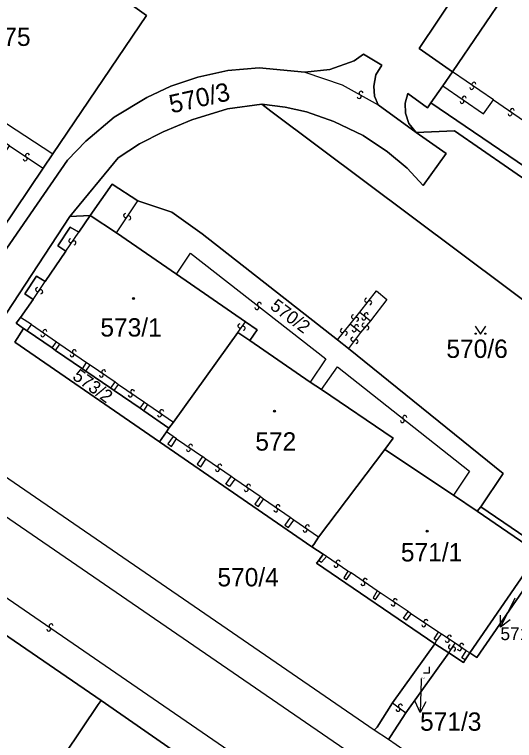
# Model space of a CAD drawing. Extents: x -600309 to -598967, y -1161267 to -1160292.
# Drawn here: x -600269.6 to -600223.2, y -1160535.7 to -1160468.5 of the extents above; entities that cross this region are included whole.
import ezdxf

# ---------------------------------------------------------------- set-up
doc = ezdxf.new("R2010")
doc.units = 0
for name, color, linetype in [('Level 1', 7, 'Continuous'), ('Level 13', 7, 'Continuous'), ('Level 3', 7, 'Continuous'), ('Level 4', 7, 'Continuous'), ('Level 5', 7, 'Continuous'), ('Level 57', 7, 'Continuous'), ('Level 60', 7, 'Continuous'), ('Vrstva 60', 7, 'Continuous')]:
    doc.layers.add(name, color=color, linetype=linetype)

msp = doc.modelspace()

# ---------------------------------------------------------------- linework, layer by layer
at = {"layer": 'Level 1'}
for points in [[(-600229, -1160473.78), (-600232.09, -1160471.61), (-600221.5, -1160455.83), (-600220, -1160454.31), (-600213.07, -1160456.09), (-600210.39, -1160453.38)], [(-600266.04, -1160481.38), (-600257.33, -1160468.55), (-600273.4, -1160457.1)], [(-600210.13, -1160470.07), (-600221.28, -1160462.46), (-600229, -1160473.78)], [(-600242.67, -1160473.81), (-600240.34, -1160473.56), (-600238.1, -1160472.77), (-600237.22, -1160472.15), (-600235.52, -1160473.17), (-600236.08, -1160474.07), (-600236.29, -1160475.1), (-600236.21, -1160476.03), (-600235.87, -1160476.84)], [(-600242.67, -1160473.81), (-600246.89, -1160473.4), (-600249.82, -1160473.65), (-600252.59, -1160474.29), (-600255.09, -1160475.12), (-600257.31, -1160476.17), (-600260.33, -1160477.98), (-600262.97, -1160480.2), (-600264.66, -1160481.97), (-600272.84, -1160493.8), (-600275.6, -1160500.4), (-600277.27, -1160506.1), (-600277.44, -1160506.49)], [(-600229, -1160473.78), (-600229.89, -1160475.08)], [(-600229.89, -1160475.08), (-600230.98, -1160476.66)], [(-600230.98, -1160476.66), (-600231.29, -1160477.11), (-600233.14, -1160475.8), (-600233.38, -1160476.69), (-600233.33, -1160477.62), (-600233.03, -1160478.56), (-600232.35, -1160479.41)], [(-600264.44, -1160487.2), (-600259.98, -1160481.76), (-600257.99, -1160480.45), (-600255.79, -1160479.33), (-600253.13, -1160478.24), (-600249.83, -1160477.22), (-600246.65, -1160476.78)], [(-600206.31, -1160506.97), (-600245.81, -1160477.42), (-600246.65, -1160476.78)], [(-600232.35, -1160479.41), (-600229.56, -1160481.35), (-600231.7, -1160484.3), (-600233.19, -1160482.71), (-600235.01, -1160481.2), (-600237.28, -1160479.69), (-600239.97, -1160478.37), (-600242.51, -1160477.5), (-600244.48, -1160477.04), (-600246.65, -1160476.78)], [(-600235.87, -1160476.84), (-600232.35, -1160479.41)], [(-600230.98, -1160476.66), (-600219.81, -1160484.24)], [(-600201.1, -1160498.22), (-600215.54, -1160488.4), (-600216.28, -1160487.9), (-600228.79, -1160479.26), (-600232.35, -1160479.41)], [(-600266.93, -1160482.72), (-600266.04, -1160481.38)], [(-600281.18, -1160503.89), (-600266.93, -1160482.72)], [(-600262.58, -1160487.1), (-600260.54, -1160484.18), (-600258.15, -1160485.74)], [(-600258.15, -1160485.74), (-600255, -1160486.77), (-600252.2, -1160488.79), (-600239.65, -1160498.61)], [(-600264.44, -1160487.2), (-600270.32, -1160496.15), (-600271.69, -1160498.68), (-600272.7, -1160501.74), (-600273.1, -1160503.69), (-600273.29, -1160505.66), (-600273.28, -1160507.64), (-600273.15, -1160508.93), (-600273.18, -1160509.41)], [(-600264.44, -1160487.2), (-600262.58, -1160487.1)], [(-600262.58, -1160487.1), (-600263.62, -1160488.65)], [(-600260.14, -1160488.69), (-600262.58, -1160487.1)], [(-600263.62, -1160488.65), (-600264.43, -1160488.18), (-600265.57, -1160489.89), (-600264.81, -1160490.41)], [(-600254.56, -1160492.52), (-600260.14, -1160488.69)], [(-600264.81, -1160490.41), (-600266.74, -1160493.22)], [(-600248.18, -1160496.94), (-600254.56, -1160492.52)], [(-600266.74, -1160493.22), (-600267.55, -1160492.72), (-600268.62, -1160494.34), (-600267.85, -1160494.89)], [(-600269.02, -1160496.53), (-600267.85, -1160494.89)], [(-600268.74, -1160497.55), (-600269.42, -1160497.08), (-600269.02, -1160496.53)], [(-600247.77, -1160498.69), (-600247.08, -1160497.7), (-600248.18, -1160496.94)], [(-600256.13, -1160508.08), (-600269.54, -1160498.83), (-600268.74, -1160497.55)], [(-600268.41, -1160497.78), (-600268.74, -1160497.55)], [(-600266.1, -1160499.36), (-600268.41, -1160497.78)], [(-600254.85, -1160506.24), (-600248.89, -1160497.92)], [(-600248.89, -1160497.92), (-600247.77, -1160498.69)], [(-600242.17, -1160502.53), (-600247.77, -1160498.69)], [(-600239.65, -1160498.61), (-600238.63, -1160499.41)], [(-600265.77, -1160499.59), (-600266.1, -1160499.36)], [(-600263.29, -1160501.29), (-600265.77, -1160499.59)], [(-600238.63, -1160499.41), (-600224.28, -1160511), (-600226.37, -1160514.09)], [(-600262.96, -1160501.51), (-600263.29, -1160501.29)], [(-600260.66, -1160503.1), (-600262.96, -1160501.51)], [(-600241.14, -1160503.23), (-600242.17, -1160502.53)], [(-600260.33, -1160503.32), (-600260.66, -1160503.1)], [(-600257.93, -1160504.96), (-600260.33, -1160503.32)], [(-600235.27, -1160508.77), (-600234.49, -1160507.73), (-600241.14, -1160503.23)], [(-600257.6, -1160505.19), (-600257.93, -1160504.96)], [(-600255.27, -1160506.81), (-600257.6, -1160505.19)], [(-600254.85, -1160506.24), (-600255.27, -1160506.81)], [(-600256.13, -1160508.08), (-600255.48, -1160507.15)], [(-600255.27, -1160506.81), (-600255.48, -1160507.15)], [(-600256.13, -1160508.08), (-600242.02, -1160517.81)], [(-600241.39, -1160516.9), (-600235.27, -1160508.77)], [(-600228.9, -1160513.02), (-600235.27, -1160508.77)], [(-600236.23, -1160534.79), (-600273.18, -1160509.41)], [(-600226.7, -1160514.5), (-600228.9, -1160513.02)], [(-600261.56, -1160532.05), (-600287.84, -1160514.02)], [(-600226.37, -1160514.09), (-600220.07, -1160518.37), (-600226.72, -1160528.04), (-600227.37, -1160527.63)], [(-600226.37, -1160514.09), (-600226.7, -1160514.5)], [(-600227.37, -1160527.63), (-600221, -1160518.37), (-600226.7, -1160514.5)], [(-600242.02, -1160517.81), (-600241.85, -1160517.59), (-600241.39, -1160516.9)], [(-600242.02, -1160517.81), (-600240.96, -1160518.49)], [(-600241.38, -1160519.05), (-600240.96, -1160518.49)], [(-600230.61, -1160526.77), (-600241.58, -1160519.3), (-600241.38, -1160519.05)], [(-600234.54, -1160532.25), (-600230.61, -1160526.77)], [(-600229.34, -1160527.61), (-600230.61, -1160526.77)], [(-600229.34, -1160527.61), (-600233.32, -1160533.18)], [(-600229.34, -1160527.61), (-600227.98, -1160528.51), (-600227.81, -1160528.27)], [(-600227.37, -1160527.63), (-600227.81, -1160528.27)], [(-600261.56, -1160532.05), (-600261.81, -1160532.42), (-600268.06, -1160541.7)], [(-600240.68, -1160546.53), (-600261.56, -1160532.05)], [(-600234.54, -1160532.25), (-600235.97, -1160534.5), (-600236.23, -1160534.79)], [(-600233.32, -1160533.18), (-600234.73, -1160535.36), (-600234.92, -1160535.66)], [(-600234.92, -1160535.66), (-600236.23, -1160534.79)], [(-600226.4, -1160541.57), (-600234.92, -1160535.66)]]:
    msp.add_lwpolyline(points, dxfattribs=at)
at = {"layer": 'Level 13'}
for centre, start, end in [((-600227.206, -1160475.231), 182.99239, 55.09039), ((-600226.995, -1160474.929), 2.77793, 235.36793), ((-600237.449, -1160475.76), 8.31813, 240.41613), ((-600237.63, -1160476.081), 188.10367, 60.69367), ((-600228.104, -1160476.522), 182.84319, 55.43319), ((-600227.895, -1160476.219), 3.05765, 235.15564), ((-600223.654, -1160477.662), 182.8714, 55.4614), ((-600223.445, -1160477.359), 3.08586, 235.18385), ((-600268.583, -1160481.832), 183.29794, 55.88794), ((-600268.376, -1160481.528), 3.5124, 235.61039), ((-600259.292, -1160487.105), 93.37006, 325.46806), ((-600258.988, -1160487.314), 273.15561, 145.74561), ((-600264.372, -1160489.425), 93.30868, 325.40668), ((-600264.068, -1160489.634), 273.09422, 145.68422), ((-600267.443, -1160493.956), 93.76191, 325.85991), ((-600267.137, -1160494.163), 273.54746, 146.13746), ((-600246.885, -1160495.336), 359.37134, 231.46934), ((-600236.944, -1160494.944), 89.03521, 321.13321), ((-600236.656, -1160495.175), 268.82076, 141.41076), ((-600247.114, -1160495.625), 179.15688, 51.74688), ((-600238.163, -1160496.484), 88.90058, 320.99857), ((-600237.876, -1160496.715), 268.68612, 141.27612), ((-600237.207, -1160496.582), 177.9326, 50.5226), ((-600236.972, -1160496.298), 358.14706, 230.24506), ((-600248.688, -1160497.32), 91.44979, 323.54778), ((-600237.874, -1160497.397), 358.42576, 231.01576), ((-600237.191, -1160497.261), 87.30104, 319.89104), ((-600236.91, -1160497.5), 267.5155, 139.61349), ((-600266.965, -1160498.151), 182.61819, 55.20819), ((-600266.754, -1160497.849), 2.83264, 234.93064), ((-600248.391, -1160497.539), 271.23533, 143.82533), ((-600239.202, -1160497.762), 88.23428, 320.33227), ((-600238.918, -1160497.997), 268.01982, 140.60982), ((-600238.107, -1160497.683), 178.64021, 50.73821), ((-600238.216, -1160498.558), 90.04142, 322.63142), ((-600237.924, -1160498.783), 270.25587, 142.35387), ((-600264.245, -1160500.011), 182.62023, 55.21023), ((-600264.034, -1160499.709), 2.83469, 234.93268), ((-600261.525, -1160501.881), 182.78683, 55.37683), ((-600261.314, -1160501.579), 3.00128, 235.09928), ((-600258.634, -1160503.419), 2.91511, 235.01311), ((-600258.845, -1160503.721), 182.70066, 55.29066), ((-600256.135, -1160505.571), 182.52629, 55.11629), ((-600255.924, -1160505.269), 2.74075, 234.83875), ((-600233.635, -1160506.094), 178.91219, 51.50219), ((-600233.404, -1160505.806), 359.12665, 231.22464), ((-600253.466, -1160508.771), 182.42559, 55.01559), ((-600253.254, -1160508.469), 2.64004, 234.73804), ((-600250.766, -1160510.631), 182.79184, 54.88984), ((-600250.555, -1160510.329), 2.57739, 235.16739), ((-600247.885, -1160512.179), 2.46313, 235.05313), ((-600248.096, -1160512.481), 182.67758, 54.77558), ((-600245.155, -1160514.079), 2.46313, 235.05313), ((-600245.366, -1160514.381), 182.67758, 54.77558), ((-600242.646, -1160516.251), 182.71646, 54.81446), ((-600242.435, -1160515.949), 2.50201, 235.09201), ((-600239.786, -1160519.511), 182.82757, 54.92557), ((-600239.575, -1160519.209), 2.61311, 235.20311), ((-600237.075, -1160520.899), 2.59934, 235.18934), ((-600237.286, -1160521.201), 182.81379, 54.91179), ((-600234.287, -1160522.788), 3.31474, 235.90474), ((-600234.494, -1160523.092), 183.52919, 55.62719), ((-600231.653, -1160525.013), 184.04431, 56.14231), ((-600231.448, -1160524.707), 3.82986, 236.41986), ((-600266.405, -1160525.421), 182.68156, 55.27156), ((-600266.194, -1160525.119), 2.89602, 234.99402), ((-600229.268, -1160526.157), 3.57163, 236.16163), ((-600229.473, -1160526.463), 183.78609, 55.88409), ((-600229.181, -1160527.064), 92.64374, 324.74173), ((-600228.124, -1160526.93), 2.16626, 234.75626), ((-600228.879, -1160527.276), 272.42928, 145.01928), ((-600228.337, -1160527.23), 182.38071, 54.47871), ((-600234.042, -1160532.856), 179.84018, 52.43018), ((-600233.817, -1160532.564), 0.05464, 232.15264)]:
    msp.add_arc(centre, 0.184, start, end, dxfattribs=at)
at = {"layer": 'Level 3'}
msp.add_line((-600308.541, -1160496.264), (-600187.53, -1160579.36), dxfattribs=at)
for points in [[(-600225.2, -1160476.38), (-600229, -1160473.78)], [(-600242.67, -1160473.81), (-600239.2, -1160474.99), (-600235.87, -1160476.84)], [(-600229.89, -1160475.08), (-600226.11, -1160477.66), (-600225.2, -1160476.38)], [(-600273.75, -1160476.35), (-600266.04, -1160481.38)], [(-600225.2, -1160476.38), (-600221.9, -1160478.63)], [(-600270.03, -1160480.64), (-600266.93, -1160482.72)], [(-600260.14, -1160488.69), (-600258.15, -1160485.74)], [(-600264.81, -1160490.41), (-600263.62, -1160488.65)], [(-600254.56, -1160492.52), (-600253.26, -1160490.58), (-600240.73, -1160500.37), (-600242.17, -1160502.53)], [(-600267.85, -1160494.89), (-600266.74, -1160493.22)], [(-600237.58, -1160496.04), (-600236.03, -1160494.08), (-600235.06, -1160494.89), (-600236.6, -1160496.84)], [(-600268.01, -1160497.2), (-600268.34, -1160496.98), (-600269.02, -1160496.53)], [(-600238.47, -1160497.16), (-600237.58, -1160496.04)], [(-600237.58, -1160496.04), (-600236.6, -1160496.84)], [(-600268.41, -1160497.78), (-600268.01, -1160497.2)], [(-600268.01, -1160497.2), (-600265.7, -1160498.79)], [(-600248.89, -1160497.92), (-600248.18, -1160496.94)], [(-600239.65, -1160498.61), (-600238.47, -1160497.16)], [(-600237.51, -1160497.93), (-600238.47, -1160497.16)], [(-600236.6, -1160496.84), (-600237.51, -1160497.93)], [(-600237.51, -1160497.93), (-600238.63, -1160499.41)], [(-600266.1, -1160499.36), (-600265.7, -1160498.79)], [(-600265.77, -1160499.59), (-600265.37, -1160499.01)], [(-600265.7, -1160498.79), (-600265.37, -1160499.01)], [(-600265.37, -1160499.01), (-600262.9, -1160500.71)], [(-600263.29, -1160501.29), (-600262.9, -1160500.71)], [(-600262.9, -1160500.71), (-600262.57, -1160500.94)], [(-600262.96, -1160501.51), (-600262.57, -1160500.94)], [(-600262.57, -1160500.94), (-600260.26, -1160502.52)], [(-600241.14, -1160503.23), (-600239.63, -1160501.13), (-600227.4, -1160510.77), (-600228.9, -1160513.02)], [(-600260.66, -1160503.1), (-600260.26, -1160502.52)], [(-600260.26, -1160502.52), (-600259.93, -1160502.75)], [(-600260.33, -1160503.32), (-600259.93, -1160502.75)], [(-600259.93, -1160502.75), (-600257.54, -1160504.39)], [(-600257.93, -1160504.96), (-600257.54, -1160504.39)], [(-600257.6, -1160505.19), (-600257.21, -1160504.61)], [(-600257.54, -1160504.39), (-600257.21, -1160504.61)], [(-600257.21, -1160504.61), (-600254.85, -1160506.24)], [(-600254.88, -1160507.57), (-600255.48, -1160507.15)], [(-600254.88, -1160507.57), (-600255.36, -1160508.26), (-600255.03, -1160508.49), (-600254.55, -1160507.79)], [(-600254.55, -1160507.79), (-600254.88, -1160507.57)], [(-600254.55, -1160507.79), (-600252.17, -1160509.44)], [(-600252.17, -1160509.44), (-600252.65, -1160510.14), (-600252.32, -1160510.37), (-600251.84, -1160509.67)], [(-600251.84, -1160509.67), (-600252.17, -1160509.44)], [(-600249.49, -1160511.29), (-600251.84, -1160509.67)], [(-600249.16, -1160511.52), (-600249.65, -1160512.22), (-600249.98, -1160511.99), (-600249.49, -1160511.29)], [(-600249.16, -1160511.52), (-600249.49, -1160511.29)], [(-600246.82, -1160513.14), (-600249.16, -1160511.52)], [(-600246.82, -1160513.14), (-600247.3, -1160513.84), (-600246.97, -1160514.07), (-600246.49, -1160513.37)], [(-600246.49, -1160513.37), (-600246.82, -1160513.14)], [(-600244.02, -1160515.08), (-600246.49, -1160513.37)], [(-600127.43, -1160613.27), (-600144.18, -1160601.67), (-600151.61, -1160596.56), (-600155.1, -1160594.14), (-600271.63, -1160514.18)], [(-600244.02, -1160515.08), (-600244.51, -1160515.78), (-600244.18, -1160516.01), (-600243.69, -1160515.31)], [(-600243.69, -1160515.31), (-600244.02, -1160515.08)], [(-600241.39, -1160516.9), (-600243.69, -1160515.31)], [(-600241.38, -1160519.05), (-600241.12, -1160519.23), (-600240.67, -1160518.68)], [(-600240.67, -1160518.68), (-600240.96, -1160518.49)], [(-600238.68, -1160520.05), (-600240.67, -1160518.68)], [(-600238.68, -1160520.05), (-600239.06, -1160520.68), (-600238.81, -1160520.83), (-600238.38, -1160520.22)], [(-600238.38, -1160520.22), (-600238.68, -1160520.05)], [(-600235.97, -1160521.88), (-600238.38, -1160520.22)], [(-600235.97, -1160521.88), (-600236.35, -1160522.52), (-600236.11, -1160522.69), (-600235.68, -1160522.07)], [(-600235.68, -1160522.07), (-600235.97, -1160521.88)], [(-600233.1, -1160523.8), (-600235.68, -1160522.07)], [(-600232.84, -1160524.01), (-600233.27, -1160524.58), (-600233.52, -1160524.41), (-600233.1, -1160523.8)], [(-600232.84, -1160524.01), (-600233.1, -1160523.8)], [(-600230.27, -1160525.7), (-600232.84, -1160524.01)], [(-600230.47, -1160526.5), (-600230.69, -1160526.32), (-600230.27, -1160525.7)], [(-600230.47, -1160526.5), (-600230.01, -1160525.88)], [(-600230.01, -1160525.88), (-600230.27, -1160525.7)], [(-600228.73, -1160526.73), (-600230.01, -1160525.88)], [(-600230.61, -1160526.77), (-600230.47, -1160526.5)], [(-600229.34, -1160527.61), (-600228.73, -1160526.73)], [(-600227.73, -1160527.43), (-600228.73, -1160526.73)], [(-600227.81, -1160528.27), (-600228.11, -1160528.09), (-600227.73, -1160527.43)], [(-600227.37, -1160527.63), (-600227.73, -1160527.43)], [(-600234.54, -1160532.25), (-600233.32, -1160533.18)]]:
    msp.add_lwpolyline(points, dxfattribs=at)
at = {"layer": 'Level 5'}
for points in [[(-600226.891, -1160497.34), (-600226.39, -1160498.09), (-600225.89, -1160497.34)], [(-600231.67, -1160529.48), (-600231.12, -1160529.48), (-600231.12, -1160528.93)]]:
    msp.add_lwpolyline(points, dxfattribs=at)
for centre, radius in [((-600258.54, -1160494.79), 0.09), ((-600258.54, -1160494.79), 0.0521), ((-600226.84, -1160498.04), 0.05), ((-600225.941, -1160498.04), 0.05), ((-600245.49, -1160505.22), 0.09), ((-600245.49, -1160505.22), 0.0521), ((-600231.34, -1160516.35), 0.09), ((-600231.34, -1160516.35), 0.0521)]:
    msp.add_circle(centre, radius, dxfattribs=at)
at = {"layer": 'Level 57'}
for p, q in [((-600223.221, -1160522.547), (-600224.544, -1160525.24)), ((-600231.885, -1160530.142), (-600231.995, -1160533.14)), ((-600231.88, -1160530), (-600231.885, -1160530.142))]:
    msp.add_line(p, q, dxfattribs=at)
for points in [[(-600223.654, -1160524.563), (-600224.544, -1160525.24), (-600224.552, -1160524.122)], [(-600231.458, -1160532.159), (-600231.995, -1160533.14), (-600232.458, -1160532.122)]]:
    msp.add_lwpolyline(points, dxfattribs=at)
at = {"layer": 'Level 60'}
for points in [[(-600221.5, -1160455.83), (-600232.09, -1160471.61), (-600229, -1160473.78), (-600229.89, -1160475.08), (-600230.98, -1160476.66), (-600231.29, -1160477.11), (-600233.14, -1160475.8), (-600233.38, -1160476.69), (-600233.33, -1160477.62), (-600233.03, -1160478.56), (-600232.35, -1160479.41), (-600235.87, -1160476.84), (-600236.21, -1160476.03), (-600236.29, -1160475.1), (-600236.08, -1160474.07), (-600235.52, -1160473.17), (-600237.22, -1160472.15), (-600238.1, -1160472.77), (-600240.34, -1160473.56), (-600242.67, -1160473.81), (-600246.89, -1160473.4), (-600249.82, -1160473.65), (-600252.59, -1160474.29), (-600255.09, -1160475.12), (-600257.31, -1160476.17), (-600260.33, -1160477.98), (-600262.97, -1160480.2), (-600264.66, -1160481.97), (-600272.84, -1160493.8)], [(-600221.28, -1160462.46), (-600229, -1160473.78), (-600232.09, -1160471.61), (-600221.5, -1160455.83)], [(-600281.18, -1160503.89), (-600266.93, -1160482.72), (-600266.04, -1160481.38), (-600257.33, -1160468.55), (-600273.4, -1160457.1)], [(-600272.84, -1160493.8), (-600264.66, -1160481.97), (-600262.97, -1160480.2), (-600260.33, -1160477.98), (-600257.31, -1160476.17), (-600255.09, -1160475.12), (-600252.59, -1160474.29), (-600249.82, -1160473.65), (-600246.89, -1160473.4), (-600242.67, -1160473.81), (-600240.34, -1160473.56), (-600238.1, -1160472.77), (-600237.22, -1160472.15), (-600235.52, -1160473.17), (-600236.08, -1160474.07), (-600236.29, -1160475.1), (-600236.21, -1160476.03), (-600235.87, -1160476.84), (-600232.35, -1160479.41), (-600229.56, -1160481.35), (-600231.7, -1160484.3), (-600233.19, -1160482.71), (-600235.01, -1160481.2), (-600237.28, -1160479.69), (-600239.97, -1160478.37), (-600242.51, -1160477.5), (-600244.48, -1160477.04), (-600246.65, -1160476.78), (-600249.83, -1160477.22), (-600253.13, -1160478.24), (-600255.79, -1160479.33), (-600257.99, -1160480.45), (-600259.98, -1160481.76), (-600264.44, -1160487.2), (-600270.32, -1160496.15)], [(-600216.28, -1160487.9), (-600228.79, -1160479.26), (-600232.35, -1160479.41), (-600233.03, -1160478.56), (-600233.33, -1160477.62), (-600233.38, -1160476.69), (-600233.14, -1160475.8), (-600231.29, -1160477.11), (-600230.98, -1160476.66), (-600219.81, -1160484.24)], [(-600226.4, -1160541.57), (-600234.92, -1160535.66), (-600234.73, -1160535.36), (-600233.32, -1160533.18), (-600229.34, -1160527.61), (-600227.98, -1160528.51), (-600227.81, -1160528.27), (-600227.37, -1160527.63), (-600226.72, -1160528.04), (-600220.07, -1160518.37), (-600226.37, -1160514.09), (-600224.28, -1160511), (-600238.63, -1160499.41), (-600239.65, -1160498.61), (-600252.2, -1160488.79), (-600255, -1160486.77), (-600258.15, -1160485.74), (-600260.54, -1160484.18), (-600262.58, -1160487.1), (-600264.44, -1160487.2), (-600259.98, -1160481.76), (-600257.99, -1160480.45), (-600255.79, -1160479.33), (-600253.13, -1160478.24), (-600249.83, -1160477.22), (-600246.65, -1160476.78), (-600245.81, -1160477.42), (-600206.31, -1160506.97)], [(-600270.32, -1160496.15), (-600264.44, -1160487.2), (-600262.58, -1160487.1), (-600263.62, -1160488.65), (-600264.43, -1160488.18), (-600265.57, -1160489.89), (-600264.81, -1160490.41), (-600266.74, -1160493.22), (-600267.55, -1160492.72), (-600268.62, -1160494.34), (-600267.85, -1160494.89), (-600269.02, -1160496.53), (-600269.42, -1160497.08), (-600268.74, -1160497.55), (-600269.54, -1160498.83), (-600256.13, -1160508.08), (-600242.02, -1160517.81), (-600240.96, -1160518.49), (-600241.38, -1160519.05), (-600241.58, -1160519.3), (-600230.61, -1160526.77), (-600234.54, -1160532.25), (-600235.97, -1160534.5), (-600236.23, -1160534.79), (-600273.18, -1160509.41)]]:
    msp.add_lwpolyline(points, dxfattribs=at)
for points in [[(-600281.18, -1160503.89), (-600290.24, -1160497.67), (-600290.08, -1160497.34), (-600289.11, -1160497.13), (-600287.66, -1160494.97), (-600286.95, -1160493.92), (-600286.6, -1160494.17), (-600286.14, -1160495.77), (-600284.73, -1160496.71), (-600282.59, -1160496.99), (-600281.53, -1160497.81), (-600270.03, -1160480.64), (-600274.59, -1160477.56), (-600275.42, -1160477.01), (-600283.63, -1160471.64), (-600282.78, -1160470.49), (-600273.4, -1160457.1), (-600257.33, -1160468.55), (-600266.04, -1160481.38), (-600266.93, -1160482.72)], [(-600221.28, -1160462.46), (-600210.13, -1160470.07), (-600217.85, -1160481.39), (-600218.74, -1160482.7), (-600219.81, -1160484.24), (-600230.98, -1160476.66), (-600229.89, -1160475.08), (-600229, -1160473.78)], [(-600204.41, -1160503.77), (-600206.31, -1160506.97), (-600245.81, -1160477.42), (-600246.65, -1160476.78), (-600244.48, -1160477.04), (-600242.51, -1160477.5), (-600239.97, -1160478.37), (-600237.28, -1160479.69), (-600235.01, -1160481.2), (-600233.19, -1160482.71), (-600231.7, -1160484.3), (-600229.56, -1160481.35), (-600232.35, -1160479.41), (-600228.79, -1160479.26), (-600216.28, -1160487.9), (-600215.54, -1160488.4), (-600201.1, -1160498.22)], [(-600262.58, -1160487.1), (-600260.54, -1160484.18), (-600258.15, -1160485.74), (-600255, -1160486.77), (-600252.2, -1160488.79), (-600239.65, -1160498.61), (-600238.63, -1160499.41), (-600224.28, -1160511), (-600226.37, -1160514.09), (-600226.7, -1160514.5), (-600228.9, -1160513.02), (-600235.27, -1160508.77), (-600234.49, -1160507.73), (-600241.14, -1160503.23), (-600242.17, -1160502.53), (-600247.77, -1160498.69), (-600247.08, -1160497.7), (-600248.18, -1160496.94), (-600254.56, -1160492.52), (-600260.14, -1160488.69)], [(-600247.08, -1160497.7), (-600247.77, -1160498.69), (-600248.89, -1160497.92), (-600254.85, -1160506.24), (-600255.27, -1160506.81), (-600257.6, -1160505.19), (-600257.93, -1160504.96), (-600260.33, -1160503.32), (-600260.66, -1160503.1), (-600262.96, -1160501.51), (-600263.29, -1160501.29), (-600265.77, -1160499.59), (-600266.1, -1160499.36), (-600268.41, -1160497.78), (-600268.74, -1160497.55), (-600269.42, -1160497.08), (-600269.02, -1160496.53), (-600267.85, -1160494.89), (-600268.62, -1160494.34), (-600267.55, -1160492.72), (-600266.74, -1160493.22), (-600264.81, -1160490.41), (-600265.57, -1160489.89), (-600264.43, -1160488.18), (-600263.62, -1160488.65), (-600262.58, -1160487.1), (-600260.14, -1160488.69), (-600254.56, -1160492.52), (-600248.18, -1160496.94)], [(-600257.93, -1160504.96), (-600257.6, -1160505.19), (-600255.27, -1160506.81), (-600255.48, -1160507.15), (-600256.13, -1160508.08), (-600269.54, -1160498.83), (-600268.74, -1160497.55), (-600268.41, -1160497.78), (-600266.1, -1160499.36), (-600265.77, -1160499.59), (-600263.29, -1160501.29), (-600262.96, -1160501.51), (-600260.66, -1160503.1), (-600260.33, -1160503.32)], [(-600247.77, -1160498.69), (-600242.17, -1160502.53), (-600241.14, -1160503.23), (-600234.49, -1160507.73), (-600235.27, -1160508.77), (-600241.39, -1160516.9), (-600241.85, -1160517.59), (-600242.02, -1160517.81), (-600256.13, -1160508.08), (-600255.48, -1160507.15), (-600255.27, -1160506.81), (-600254.85, -1160506.24), (-600248.89, -1160497.92)], [(-600228.9, -1160513.02), (-600226.7, -1160514.5), (-600221, -1160518.37), (-600227.37, -1160527.63), (-600227.81, -1160528.27), (-600227.98, -1160528.51), (-600229.34, -1160527.61), (-600230.61, -1160526.77), (-600241.58, -1160519.3), (-600241.38, -1160519.05), (-600240.96, -1160518.49), (-600242.02, -1160517.81), (-600241.85, -1160517.59), (-600241.39, -1160516.9), (-600235.27, -1160508.77)], [(-600226.7, -1160514.5), (-600226.37, -1160514.09), (-600220.07, -1160518.37), (-600226.72, -1160528.04), (-600227.37, -1160527.63), (-600221, -1160518.37)], [(-600230.61, -1160526.77), (-600229.34, -1160527.61), (-600233.32, -1160533.18), (-600234.73, -1160535.36), (-600234.92, -1160535.66), (-600236.23, -1160534.79), (-600235.97, -1160534.5), (-600234.54, -1160532.25)], [(-600261.56, -1160532.05), (-600240.68, -1160546.53), (-600242.26, -1160547.7), (-600243.63, -1160548.48), (-600245.28, -1160549.19), (-600247.17, -1160549.73), (-600248.4, -1160549.94), (-600249.68, -1160550.04), (-600251.1, -1160550.01), (-600252.75, -1160549.83), (-600254.76, -1160549.31), (-600256.51, -1160548.58), (-600268.06, -1160541.7), (-600261.81, -1160532.42)]]:
    msp.add_lwpolyline(points, close=True, dxfattribs=at)
at = {"layer": 'Vrstva 60'}
for points in [[(-600226.4, -1160541.57), (-600234.92, -1160535.66), (-600236.23, -1160534.79), (-600273.18, -1160509.41), (-600277.44, -1160506.49), (-600281.18, -1160503.89), (-600290.24, -1160497.67), (-600293.77, -1160495.29), (-600295.54, -1160494.09), (-600298.15, -1160492.32), (-600298.44, -1160492.13), (-600301.11, -1160490.31), (-600308.541, -1160485.2), (-600308.541, -1160499.81), (-600287.84, -1160514.02), (-600261.56, -1160532.05), (-600240.68, -1160546.53)], [(-600268.06, -1160541.7), (-600261.81, -1160532.42), (-600261.56, -1160532.05), (-600287.84, -1160514.02), (-600297.78, -1160528.33), (-600298.89, -1160530.07), (-600308.541, -1160544.31)]]:
    msp.add_lwpolyline(points, dxfattribs=at)

# ---------------------------------------------------------------- texts
at = {"layer": 'Level 4'}
for s, height, p in [('575', 1.7, (-600271.88, -1160471.38)), ('573/1', 1.7, (-600261.62, -1160498.31)), ('570/6', 1.7, (-600229.55, -1160500.29)), ('572', 1.7, (-600247.26, -1160508.88)), ('571/1', 1.7, (-600233.77, -1160519.15)), ('570/4', 1.7, (-600250.77, -1160521.46)), ('571/3', 0.1, (-600231.88, -1160530))]:
    msp.add_text(s, height=height, dxfattribs=at).set_placement(p)
for s, height, rotation, p in [('570/3', 1.7, 12.6, (-600255.04, -1160477.64)), ('570/2', 1.2, 323.1, (-600245.97, -1160495.68)), ('573/2', 1.2, 324, (-600264.29, -1160502.18))]:
    msp.add_text(s, height=height, rotation=rotation, dxfattribs=at).set_placement(p)
at = {"layer": 'Level 57'}
for s, height, p in [('571/2', 1.2, (-600224.544, -1160526.44)), ('571/3', 1.7, (-600231.995, -1160534.84))]:
    msp.add_text(s, height=height, dxfattribs=at).set_placement(p)

doc.saveas('drawing.dxf')
